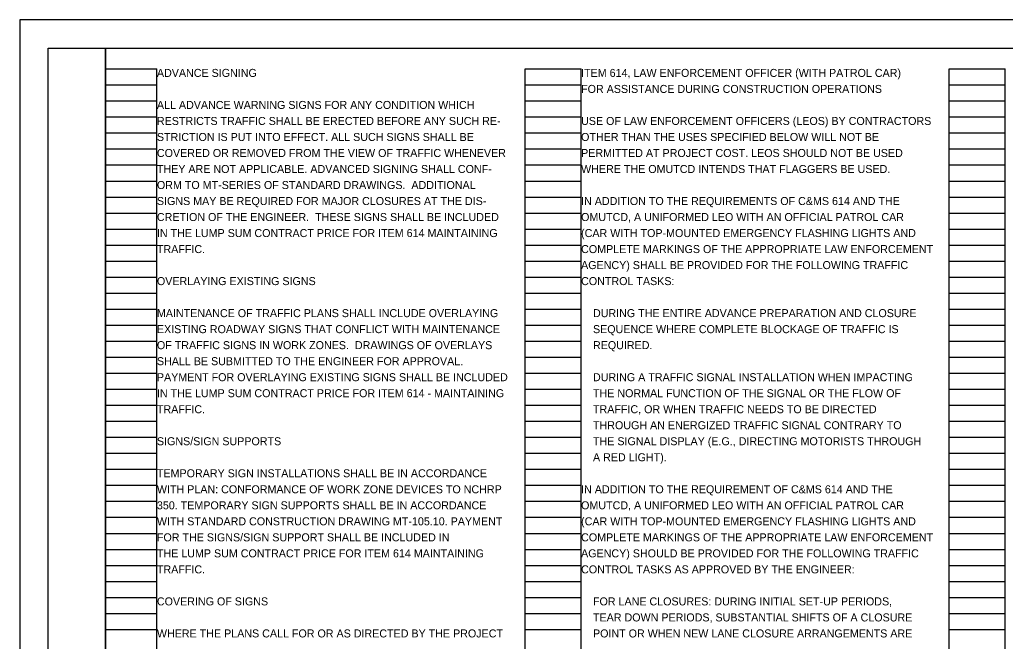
# Model space of a CAD drawing. Extents: x 0 to 34, y 0 to 22.
# Drawn here: x 0 to 17.24, y 11.13 to 22 of the extents above; entities that cross this region are included whole.
import ezdxf

# ---------------------------------------------------------------- set-up
doc = ezdxf.new("R2010")
doc.units = 0
for name, color, linetype in [('MT_P_Text', 7, 'Continuous'), ('SH_Border', 7, 'Continuous'), ('SH_Cut_Line', 7, 'Continuous'), ('SH_Data', 7, 'Continuous'), ('SH_Text', 7, 'Continuous'), ('TX_P_Misc', 7, 'Continuous')]:
    doc.layers.add(name, color=color, linetype=linetype)

msp = doc.modelspace()

# ---------------------------------------------------------------- linework, layer by layer
at = {"layer": 'SH_Border'}
for points in [[(0.5, 21.5), (1.5, 21.5), (1.5, 0.5), (0.5, 0.5)], [(1.5, 21.5), (33.5, 21.5), (33.5, 0.5), (1.5, 0.5)]]:
    msp.add_lwpolyline(points, close=True, dxfattribs=at)
at = {"layer": 'SH_Cut_Line'}
msp.add_lwpolyline([(0, 0), (34, 0), (34, 22), (0, 22)], close=True, dxfattribs=at)
at = {"layer": 'SH_Data'}
for p, q in [((1.5, 0.98), (1.5, 21.14)), ((1.5, 21.14), (2.4, 21.14)), ((2.4, 0.98), (2.4, 21.14)), ((8.84, 0.98), (8.84, 21.14)), ((8.84, 21.14), (9.82, 21.14)), ((9.82, 0.98), (9.82, 21.14)), ((16.26, 0.98), (16.26, 21.14)), ((16.26, 21.14), (17.24, 21.14)), ((17.24, 0.98), (17.24, 21.14)), ((1.5, 20.86), (2.4, 20.86)), ((8.84, 20.86), (9.82, 20.86)), ((16.26, 20.86), (17.24, 20.86)), ((1.5, 20.58), (2.4, 20.58)), ((8.84, 20.58), (9.82, 20.58)), ((16.26, 20.58), (17.24, 20.58)), ((1.5, 20.3), (2.4, 20.3)), ((8.84, 20.3), (9.82, 20.3)), ((16.26, 20.3), (17.24, 20.3)), ((1.5, 20.02), (2.4, 20.02)), ((8.84, 20.02), (9.82, 20.02)), ((16.26, 20.02), (17.24, 20.02)), ((1.5, 19.74), (2.4, 19.74)), ((8.84, 19.74), (9.82, 19.74)), ((16.26, 19.74), (17.24, 19.74)), ((1.5, 19.46), (2.4, 19.46)), ((8.84, 19.46), (9.82, 19.46)), ((16.26, 19.46), (17.24, 19.46)), ((1.5, 19.18), (2.4, 19.18)), ((8.84, 19.18), (9.82, 19.18)), ((16.26, 19.18), (17.24, 19.18)), ((1.5, 18.9), (2.4, 18.9)), ((8.84, 18.9), (9.82, 18.9)), ((16.26, 18.9), (17.24, 18.9)), ((1.5, 18.62), (2.4, 18.62)), ((8.84, 18.62), (9.82, 18.62)), ((16.26, 18.62), (17.24, 18.62)), ((1.5, 18.34), (2.4, 18.34)), ((8.84, 18.34), (9.82, 18.34)), ((16.26, 18.34), (17.24, 18.34)), ((1.5, 18.06), (2.4, 18.06)), ((8.84, 18.06), (9.82, 18.06)), ((16.26, 18.06), (17.24, 18.06)), ((1.5, 17.78), (2.4, 17.78)), ((8.84, 17.78), (9.82, 17.78)), ((16.26, 17.78), (17.24, 17.78)), ((1.5, 17.5), (2.4, 17.5)), ((8.84, 17.5), (9.82, 17.5)), ((16.26, 17.5), (17.24, 17.5)), ((1.5, 17.22), (2.4, 17.22)), ((8.84, 17.22), (9.82, 17.22)), ((16.26, 17.22), (17.24, 17.22)), ((1.5, 16.94), (2.4, 16.94)), ((8.84, 16.94), (9.82, 16.94)), ((16.26, 16.94), (17.24, 16.94)), ((1.5, 16.66), (2.4, 16.66)), ((8.84, 16.66), (9.82, 16.66)), ((16.26, 16.66), (17.24, 16.66)), ((1.5, 16.38), (2.4, 16.38)), ((8.84, 16.38), (9.82, 16.38)), ((16.26, 16.38), (17.24, 16.38)), ((1.5, 16.1), (2.4, 16.1)), ((8.84, 16.1), (9.82, 16.1)), ((16.26, 16.1), (17.24, 16.1)), ((1.5, 15.82), (2.4, 15.82)), ((8.84, 15.82), (9.82, 15.82)), ((16.26, 15.82), (17.24, 15.82)), ((1.5, 15.54), (2.4, 15.54)), ((8.84, 15.54), (9.82, 15.54)), ((16.26, 15.54), (17.24, 15.54)), ((1.5, 15.26), (2.4, 15.26)), ((8.84, 15.26), (9.82, 15.26)), ((16.26, 15.26), (17.24, 15.26)), ((1.5, 14.98), (2.4, 14.98)), ((8.84, 14.98), (9.82, 14.98)), ((16.26, 14.98), (17.24, 14.98)), ((1.5, 14.7), (2.4, 14.7)), ((8.84, 14.7), (9.82, 14.7)), ((16.26, 14.7), (17.24, 14.7)), ((1.5, 14.42), (2.4, 14.42)), ((8.84, 14.42), (9.82, 14.42)), ((16.26, 14.42), (17.24, 14.42)), ((1.5, 14.14), (2.4, 14.14)), ((8.84, 14.14), (9.82, 14.14)), ((16.26, 14.14), (17.24, 14.14)), ((1.5, 13.86), (2.4, 13.86)), ((8.84, 13.86), (9.82, 13.86)), ((16.26, 13.86), (17.24, 13.86)), ((1.5, 13.58), (2.4, 13.58)), ((8.84, 13.58), (9.82, 13.58)), ((16.26, 13.58), (17.24, 13.58)), ((1.5, 13.3), (2.4, 13.3)), ((8.84, 13.3), (9.82, 13.3)), ((16.26, 13.3), (17.24, 13.3)), ((1.5, 13.02), (2.4, 13.02)), ((8.84, 13.02), (9.82, 13.02)), ((16.26, 13.02), (17.24, 13.02)), ((1.5, 12.74), (2.4, 12.74)), ((8.84, 12.74), (9.82, 12.74)), ((16.26, 12.74), (17.24, 12.74)), ((1.5, 12.46), (2.4, 12.46)), ((8.84, 12.46), (9.82, 12.46)), ((16.26, 12.46), (17.24, 12.46)), ((1.5, 12.18), (2.4, 12.18)), ((8.84, 12.18), (9.82, 12.18)), ((16.26, 12.18), (17.24, 12.18)), ((1.5, 11.9), (2.4, 11.9)), ((8.84, 11.9), (9.82, 11.9)), ((16.26, 11.9), (17.24, 11.9)), ((1.5, 11.62), (2.4, 11.62)), ((8.84, 11.62), (9.82, 11.62)), ((16.26, 11.62), (17.24, 11.62)), ((1.5, 11.34), (2.4, 11.34)), ((8.84, 11.34), (9.82, 11.34)), ((16.26, 11.34), (17.24, 11.34))]:
    msp.add_line(p, q, dxfattribs=at)

# ---------------------------------------------------------------- texts
at = {"layer": 'MT_P_Text'}
for s, p in [('ALL ADVANCE WARNING SIGNS FOR ANY CONDITION WHICH', (2.4, 20.44)), ('RESTRICTS TRAFFIC SHALL BE ERECTED BEFORE ANY SUCH RE-', (2.4, 20.16)), ('STRICTION IS PUT INTO EFFECT. ALL SUCH SIGNS SHALL BE', (2.4, 19.88)), ('COVERED OR REMOVED FROM THE VIEW OF TRAFFIC WHENEVER', (2.4, 19.6)), ('THEY ARE NOT APPLICABLE. ADVANCED SIGNING SHALL CONF-', (2.4, 19.32)), ('ORM TO MT-SERIES OF STANDARD DRAWINGS.  ADDITIONAL', (2.4, 19.04)), ('SIGNS MAY BE REQUIRED FOR MAJOR CLOSURES AT THE DIS-', (2.4, 18.76)), ('CRETION OF THE ENGINEER.  THESE SIGNS SHALL BE INCLUDED', (2.4, 18.48)), ('IN THE LUMP SUM CONTRACT PRICE FOR ITEM 614 MAINTAINING', (2.4, 18.2)), ('TRAFFIC.', (2.4, 17.92)), ('MAINTENANCE OF TRAFFIC PLANS SHALL INCLUDE OVERLAYING', (2.4, 16.8)), ('EXISTING ROADWAY SIGNS THAT CONFLICT WITH MAINTENANCE', (2.4, 16.52)), ('OF TRAFFIC SIGNS IN WORK ZONES.  DRAWINGS OF OVERLAYS', (2.4, 16.24)), ('SHALL BE SUBMITTED TO THE ENGINEER FOR APPROVAL.  ', (2.4, 15.96)), ('PAYMENT FOR OVERLAYING EXISTING SIGNS SHALL BE INCLUDED', (2.4, 15.68)), ('IN THE LUMP SUM CONTRACT PRICE FOR ITEM 614 - MAINTAINING', (2.4, 15.4)), ('TRAFFIC.', (2.4, 15.12)), ('TEMPORARY SIGN INSTALLATIONS SHALL BE IN ACCORDANCE', (2.4, 14)), ('WITH PLAN: CONFORMANCE OF WORK ZONE DEVICES TO NCHRP', (2.4, 13.72)), ('350. TEMPORARY SIGN SUPPORTS SHALL BE IN ACCORDANCE', (2.4, 13.44)), ('WITH STANDARD CONSTRUCTION DRAWING MT-105.10. PAYMENT', (2.4, 13.16)), ('FOR THE SIGNS/SIGN SUPPORT SHALL BE INCLUDED IN', (2.4, 12.88)), ('THE LUMP SUM CONTRACT PRICE FOR ITEM 614 MAINTAINING', (2.4, 12.6)), ('TRAFFIC.', (2.4, 12.32)), ('WHERE THE PLANS CALL FOR OR AS DIRECTED BY THE PROJECT', (2.4, 11.2))]:
    msp.add_text(s, height=0.14, dxfattribs=at).set_placement(p)
at = {"layer": 'SH_Text'}
for s, p in [('ITEM 614, LAW ENFORCEMENT OFFICER (WITH PATROL CAR)', (9.82, 21)), ('FOR ASSISTANCE DURING CONSTRUCTION OPERATIONS', (9.82, 20.72)), ('USE OF LAW ENFORCEMENT OFFICERS (LEOS) BY CONTRACTORS', (9.82, 20.16)), ('OTHER THAN THE USES SPECIFIED BELOW WILL NOT BE', (9.82, 19.88)), ('PERMITTED AT PROJECT COST. LEOS SHOULD NOT BE USED', (9.82, 19.6)), ('WHERE THE OMUTCD INTENDS THAT FLAGGERS BE USED.', (9.82, 19.32)), ('IN ADDITION TO THE REQUIREMENTS OF C&MS 614 AND THE', (9.82, 18.76)), ('OMUTCD, A UNIFORMED LEO WITH AN OFFICIAL PATROL CAR', (9.82, 18.48)), ('(CAR WITH TOP-MOUNTED EMERGENCY FLASHING LIGHTS AND', (9.82, 18.2)), ('COMPLETE MARKINGS OF THE APPROPRIATE LAW ENFORCEMENT', (9.82, 17.92)), ('AGENCY) SHALL BE PROVIDED FOR THE FOLLOWING TRAFFIC', (9.82, 17.64)), ('CONTROL TASKS:', (9.82, 17.36)), ('    DURING THE ENTIRE ADVANCE PREPARATION AND CLOSURE', (9.82, 16.8)), ('    SEQUENCE WHERE COMPLETE BLOCKAGE OF TRAFFIC IS', (9.82, 16.52)), ('    REQUIRED.', (9.82, 16.24)), ('    DURING A TRAFFIC SIGNAL INSTALLATION WHEN IMPACTING', (9.82, 15.68)), ('    THE NORMAL FUNCTION OF THE SIGNAL OR THE FLOW OF', (9.82, 15.4)), ('    TRAFFIC, OR WHEN TRAFFIC NEEDS TO BE DIRECTED', (9.82, 15.12)), ('    THROUGH AN ENERGIZED TRAFFIC SIGNAL CONTRARY TO', (9.82, 14.84)), ('    THE SIGNAL DISPLAY (E.G., DIRECTING MOTORISTS THROUGH', (9.82, 14.56)), ('    A RED LIGHT).', (9.82, 14.28)), ('IN ADDITION TO THE REQUIREMENT OF C&MS 614 AND THE', (9.82, 13.72)), ('OMUTCD, A UNIFORMED LEO WITH AN OFFICIAL PATROL CAR', (9.82, 13.44)), ('(CAR WITH TOP-MOUNTED EMERGENCY FLASHING LIGHTS AND', (9.82, 13.16)), ('COMPLETE MARKINGS OF THE APPROPRIATE LAW ENFORCEMENT', (9.82, 12.88)), ('AGENCY) SHOULD BE PROVIDED FOR THE FOLLOWING TRAFFIC', (9.82, 12.6)), ('CONTROL TASKS AS APPROVED BY THE ENGINEER:', (9.82, 12.32)), ('    FOR LANE CLOSURES: DURING INITIAL SET-UP PERIODS,', (9.82, 11.76)), ('    TEAR DOWN PERIODS, SUBSTANTIAL SHIFTS OF A CLOSURE', (9.82, 11.48)), ('    POINT OR WHEN NEW LANE CLOSURE ARRANGEMENTS ARE', (9.82, 11.2))]:
    msp.add_text(s, height=0.14, dxfattribs=at).set_placement(p)
at = {"layer": 'TX_P_Misc'}
for s, p in [('ADVANCE SIGNING', (2.4, 21)), ('OVERLAYING EXISTING SIGNS', (2.4, 17.36)), ('SIGNS/SIGN SUPPORTS', (2.4, 14.56)), ('COVERING OF SIGNS', (2.4, 11.76))]:
    msp.add_text(s, height=0.14, dxfattribs=at).set_placement(p)

doc.saveas('drawing.dxf')
